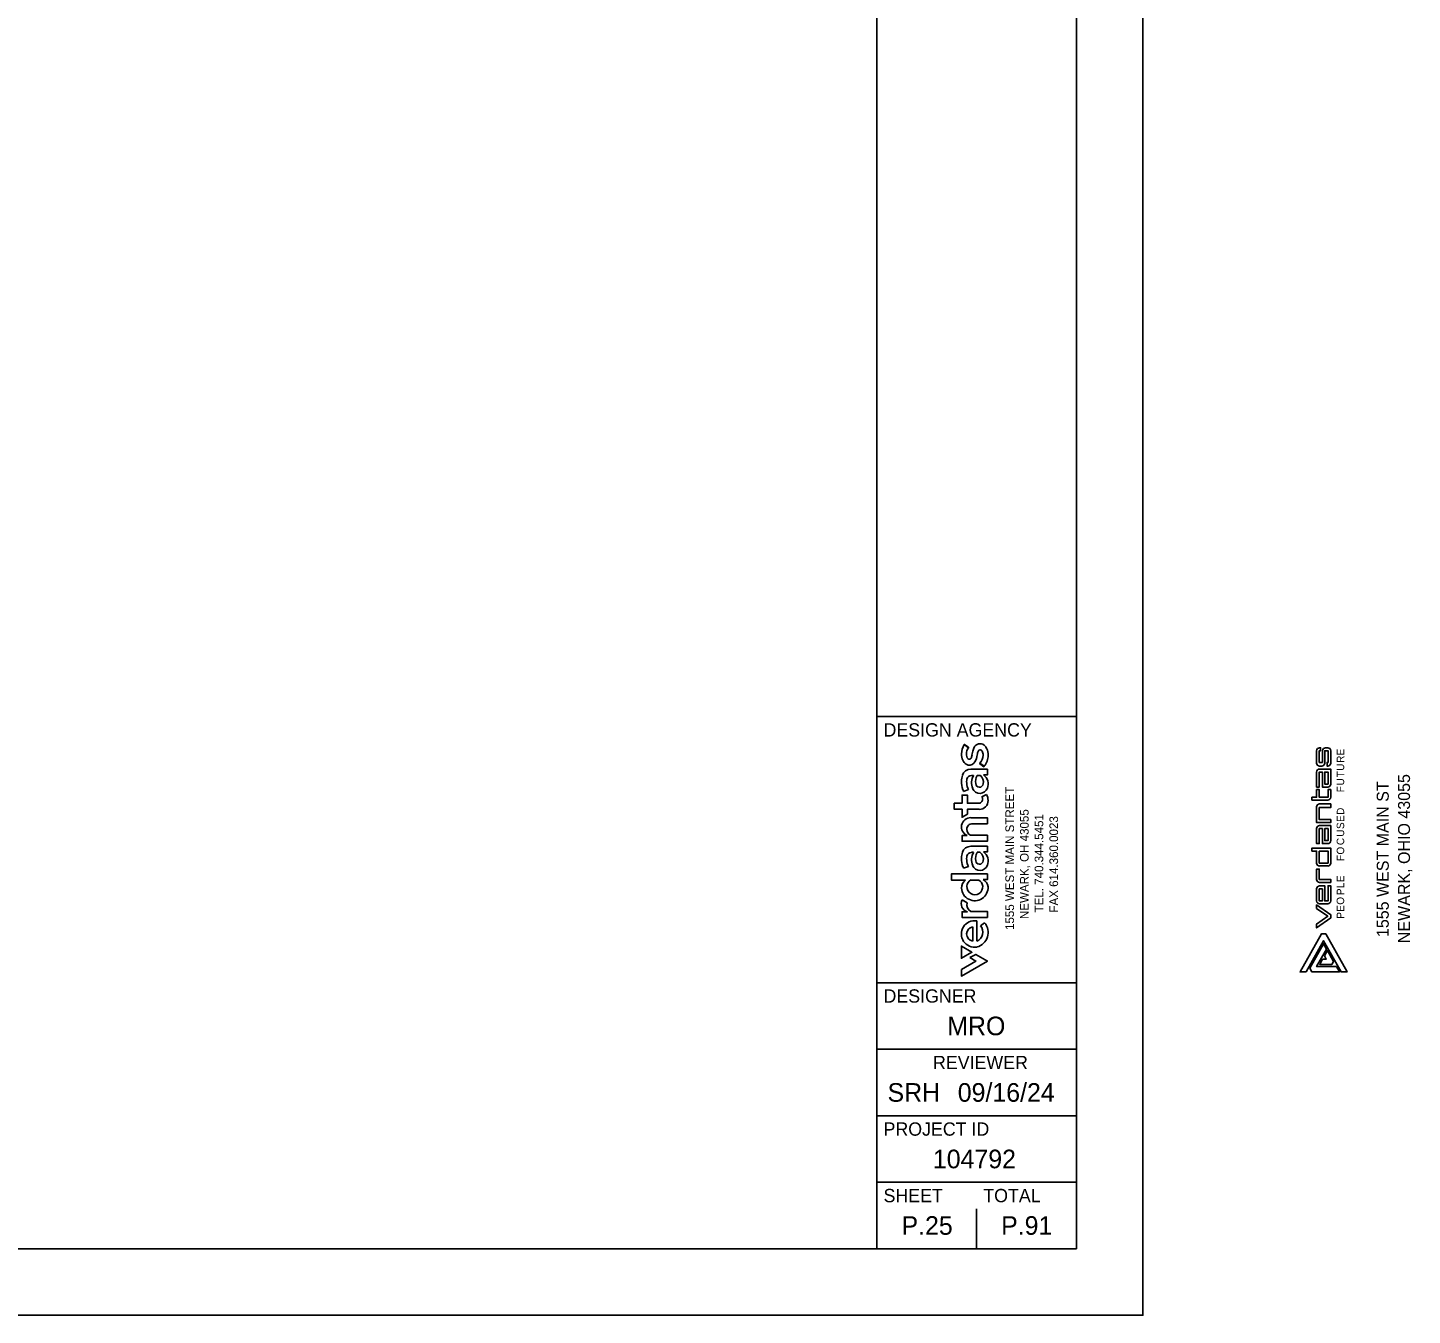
# Model space of a CAD drawing. Extents: x 0 to 36, y 0 to 22.
# Drawn here: x 25.62 to 36.03, y 0 to 9.68 of the extents above; entities that cross this region are included whole.
import ezdxf

# ---------------------------------------------------------------- set-up
doc = ezdxf.new("R2010")
doc.units = 0
for name, color, linetype in [('CS-ANNO-TTLB-LOGO', 7, 'Continuous'), ('Default', 7, 'Continuous'), ('SH_Border', 7, 'Continuous'), ('SH_Cut_Line', 7, 'Continuous'), ('SH_Data', 7, 'Continuous'), ('SH_Text', 7, 'Continuous')]:
    doc.layers.add(name, color=color, linetype=linetype)

msp = doc.modelspace()

# ---------------------------------------------------------------- linework, layer by layer
at = {"layer": 'CS-ANNO-TTLB-LOGO'}
for p, q in [((35.305, 4.243), (35.305, 4.15)), ((35.336, 4.266), (35.328, 4.266)), ((35.389, 4.266), (35.373, 4.266)), ((35.412, 4.15), (35.412, 4.243)), ((35.305, 3.97), (35.305, 4.083)), ((35.328, 4.128), (35.344, 4.128)), ((35.305, 3.546), (35.305, 3.658)), ((35.328, 3.377), (35.389, 3.377)), ((35.412, 3.115), (35.412, 3.228)), ((35.305, 3.205), (35.305, 3.115)), ((35.328, 3.093), (35.389, 3.093))]:
    msp.add_line(p, q, dxfattribs=at)
for points in [[(35.35, 4.243), (35.35, 4.156), (35.325, 4.156), (35.325, 4.243), (35.336, 4.243), (35.336, 4.266)], [(35.367, 4.15), (35.367, 4.243), (35.392, 4.243), (35.392, 4.156), (35.384, 4.156), (35.384, 4.128), (35.389, 4.128)], [(35.389, 3.97), (35.35, 3.97), (35.35, 4.083), (35.325, 4.083), (35.325, 3.97), (35.305, 3.97)], [(35.328, 4.105), (35.412, 4.105), (35.412, 3.993)], [(35.27, 3.894), (35.305, 3.894), (35.305, 3.951), (35.325, 3.951), (35.325, 3.894), (35.392, 3.894), (35.392, 3.951), (35.412, 3.951), (35.412, 3.894)], [(35.389, 3.872), (35.27, 3.872), (35.27, 3.894)], [(35.305, 3.821), (35.305, 3.703), (35.412, 3.703), (35.412, 3.726), (35.325, 3.726), (35.325, 3.816), (35.412, 3.816)], [(35.412, 3.816), (35.412, 3.844), (35.328, 3.844)], [(35.389, 3.546), (35.35, 3.546), (35.35, 3.658), (35.325, 3.658), (35.325, 3.546), (35.305, 3.546)], [(35.328, 3.681), (35.412, 3.681), (35.412, 3.568)], [(35.27, 3.512), (35.27, 3.489), (35.305, 3.489), (35.305, 3.399)], [(35.412, 3.399), (35.412, 3.512), (35.27, 3.512)], [(35.412, 3.276), (35.325, 3.276), (35.325, 3.354), (35.305, 3.354), (35.305, 3.276)], [(35.328, 3.253), (35.412, 3.253), (35.412, 3.276)], [(35.412, 3.228), (35.392, 3.228), (35.392, 3.115), (35.367, 3.115), (35.367, 3.228), (35.328, 3.228)]]:
    msp.add_lwpolyline(points, dxfattribs=at)
for points in [[(35.367, 4.083), (35.392, 4.083), (35.392, 3.993), (35.367, 3.993)], [(35.367, 3.658), (35.392, 3.658), (35.392, 3.568), (35.367, 3.568)], [(35.325, 3.489), (35.325, 3.399), (35.392, 3.399), (35.392, 3.489)], [(35.35, 3.205), (35.325, 3.205), (35.325, 3.115), (35.35, 3.115)], [(35.39, 2.999), (35.305, 2.94), (35.305, 2.912), (35.412, 2.987), (35.412, 3.011), (35.306, 3.085), (35.305, 3.058)]]:
    msp.add_lwpolyline(points, close=True, dxfattribs=at)
for centre, start, end in [((35.328, 4.243), 90, 180), ((35.373, 4.243), 90, 180), ((35.389, 4.243), 360, 90), ((35.328, 4.15), 180, 270), ((35.328, 4.083), 90, 180), ((35.344, 4.15), 270, 0), ((35.389, 4.15), 270, 0), ((35.389, 3.993), 270, 360), ((35.389, 3.894), 270, 360), ((35.328, 3.821), 90, 180), ((35.328, 3.658), 90, 180), ((35.389, 3.568), 270, 360), ((35.328, 3.399), 180, 270), ((35.389, 3.399), 270, 0), ((35.328, 3.276), 180, 270), ((35.328, 3.205), 90, 180), ((35.328, 3.115), 180, 270), ((35.389, 3.115), 270, 0)]:
    msp.add_arc(centre, 0.0225, start, end, dxfattribs=at)
at = {"layer": 'Default'}
for p, q in [((35.305, 4.243), (35.305, 4.15)), ((35.389, 4.266), (35.373, 4.266)), ((35.412, 4.15), (35.412, 4.243)), ((35.328, 4.128), (35.344, 4.128)), ((35.328, 3.377), (35.389, 3.377)), ((35.305, 3.205), (35.305, 3.115)), ((35.328, 3.093), (35.389, 3.093)), ((35.255, 2.609), (35.358, 2.792)), ((35.381, 2.752), (35.306, 2.621)), ((35.358, 2.792), (35.381, 2.752)), ((35.27, 2.581), (35.255, 2.609)), ((35.306, 2.621), (35.455, 2.621)), ((35.455, 2.621), (35.477, 2.581)), ((35.477, 2.581), (35.27, 2.581))]:
    msp.add_line(p, q, dxfattribs=at)
for points in [[(35.35, 4.243), (35.35, 4.156), (35.325, 4.156), (35.325, 4.243), (35.336, 4.243), (35.336, 4.266), (35.328, 4.266)], [(35.367, 4.15), (35.367, 4.243), (35.392, 4.243), (35.392, 4.156), (35.384, 4.156), (35.384, 4.128), (35.389, 4.128)], [(35.305, 4.083), (35.305, 3.97), (35.325, 3.97), (35.325, 4.083), (35.35, 4.083), (35.35, 3.97), (35.389, 3.97)], [(35.412, 3.993), (35.412, 4.105), (35.328, 4.105)], [(35.412, 3.894), (35.412, 3.951), (35.392, 3.951), (35.392, 3.894), (35.325, 3.894), (35.325, 3.951), (35.305, 3.951), (35.305, 3.894), (35.27, 3.894), (35.27, 3.872), (35.389, 3.872)], [(35.305, 3.821), (35.305, 3.703), (35.412, 3.703), (35.412, 3.726), (35.325, 3.726), (35.325, 3.816), (35.412, 3.816), (35.412, 3.844), (35.328, 3.844)], [(35.305, 3.658), (35.305, 3.546), (35.325, 3.546), (35.325, 3.658), (35.35, 3.658), (35.35, 3.546), (35.389, 3.546)], [(35.412, 3.568), (35.412, 3.681), (35.328, 3.681)], [(35.412, 3.399), (35.412, 3.512), (35.27, 3.512), (35.27, 3.489), (35.305, 3.489), (35.305, 3.399)], [(35.328, 3.253), (35.412, 3.253), (35.412, 3.276), (35.325, 3.276), (35.325, 3.354), (35.305, 3.354), (35.305, 3.276)], [(35.412, 3.115), (35.412, 3.228), (35.392, 3.228), (35.392, 3.115), (35.367, 3.115), (35.367, 3.228), (35.328, 3.228)]]:
    msp.add_lwpolyline(points, dxfattribs=at)
for points in [[(35.392, 4.083), (35.392, 3.993), (35.367, 3.993), (35.367, 4.083)], [(35.392, 3.658), (35.392, 3.568), (35.367, 3.568), (35.367, 3.658)], [(35.325, 3.489), (35.392, 3.489), (35.392, 3.399), (35.325, 3.399)], [(35.35, 3.205), (35.35, 3.115), (35.325, 3.115), (35.325, 3.205)], [(35.305, 2.94), (35.305, 2.912), (35.412, 2.987), (35.412, 3.011), (35.306, 3.085), (35.305, 3.058), (35.39, 2.999)], [(35.358, 2.815), (35.49, 2.581), (35.535, 2.581), (35.374, 2.867), (35.342, 2.867), (35.181, 2.581), (35.226, 2.581)], [(35.226, 2.581), (35.358, 2.815), (35.49, 2.581), (35.535, 2.581), (35.374, 2.867), (35.342, 2.867), (35.181, 2.581)], [(35.255, 2.609), (35.27, 2.581), (35.477, 2.581), (35.455, 2.621), (35.306, 2.621), (35.381, 2.752), (35.358, 2.792)], [(35.351, 2.677), (35.329, 2.637), (35.419, 2.637), (35.432, 2.66), (35.387, 2.741), (35.364, 2.701), (35.378, 2.677)], [(35.351, 2.677), (35.378, 2.677), (35.364, 2.701), (35.387, 2.741), (35.432, 2.66), (35.419, 2.637), (35.329, 2.637)]]:
    msp.add_lwpolyline(points, close=True, dxfattribs=at)
for centre, start, end in [((35.328, 4.243), 90, 180), ((35.373, 4.243), 90, 180), ((35.389, 4.243), 360, 90), ((35.328, 4.15), 180, 270), ((35.328, 4.083), 90, 180), ((35.344, 4.15), 270, 0), ((35.389, 4.15), 270, 0), ((35.389, 3.993), 270, 0), ((35.389, 3.894), 270, 0), ((35.328, 3.821), 90, 180), ((35.328, 3.658), 90, 180), ((35.389, 3.568), 270, 0), ((35.328, 3.399), 180, 270), ((35.389, 3.399), 270, 0), ((35.328, 3.276), 180, 270), ((35.328, 3.205), 90, 180), ((35.328, 3.115), 180, 270), ((35.389, 3.115), 270, 0)]:
    msp.add_arc(centre, 0.0225, start, end, dxfattribs=at)
at = {"layer": 'SH_Border'}
for p, q in [((32, 0.5), (32, 21.5)), ((32, 4.5), (33.5, 4.5)), ((32, 2.5), (33.5, 2.5)), ((32, 2), (33.5, 2)), ((32, 1.5), (33.5, 1.5)), ((32, 1), (33.5, 1))]:
    msp.add_line(p, q, dxfattribs=at)
msp.add_lwpolyline([(1.5, 21.5), (33.5, 21.5), (33.5, 0.5), (1.5, 0.5)], close=True, dxfattribs=at)
at = {"layer": 'SH_Cut_Line'}
msp.add_lwpolyline([(0, 0), (34, 0), (34, 22), (0, 22)], close=True, dxfattribs=at)
at = {"layer": 'SH_Data'}
for p, q in [((32.75, 3.5), (32.75, 3.5)), ((32.75, 0.5), (32.75, 0.8)), ((32.375, 0.675), (32.375, 0.675))]:
    msp.add_line(p, q, dxfattribs=at)
at = {"layer": 'SH_Text'}
for p, q in [((32.688, 4.266), (32.657, 4.29)), ((32.722, 4.24), (32.715, 4.209)), ((32.751, 4.199), (32.756, 4.219)), ((32.774, 4.151), (32.807, 4.127)), ((32.711, 4.058), (32.727, 4.058)), ((32.753, 4.058), (32.776, 4.058)), ((32.648, 3.95), (32.652, 3.938)), ((32.825, 3.914), (32.79, 3.898)), ((32.711, 3.48), (32.727, 3.48)), ((32.753, 3.48), (32.776, 3.48)), ((32.648, 3.372), (32.652, 3.36)), ((32.706, 3.271), (32.766, 3.271)), ((32.679, 3.1), (32.642, 3.122)), ((32.721, 2.92), (32.721, 2.812)), ((32.751, 2.811), (32.751, 2.964)), ((32.81, 2.95), (32.778, 2.928))]:
    msp.add_line(p, q, dxfattribs=at)
for points in [[(32.689, 4.269), (32.658, 4.291), (32.657, 4.29)], [(32.688, 4.266), (32.689, 4.269)], [(32.722, 4.24), (32.715, 4.209)], [(32.751, 4.199), (32.756, 4.219)], [(32.801, 4.062), (32.831, 4.062), (32.831, 4.104), (32.706, 4.104)], [(32.801, 4.062), (32.831, 4.062), (32.831, 4.104), (32.706, 4.104)], [(32.774, 4.151), (32.772, 4.148), (32.803, 4.123), (32.807, 4.127)], [(32.652, 3.938), (32.688, 3.953), (32.684, 3.962)], [(32.652, 3.938), (32.688, 3.953), (32.684, 3.962)], [(32.711, 4.058), (32.727, 4.058)], [(32.776, 4.058), (32.753, 4.058)], [(32.762, 3.849), (32.68, 3.849), (32.68, 3.91), (32.641, 3.91), (32.641, 3.849), (32.582, 3.849), (32.582, 3.803), (32.641, 3.803), (32.641, 3.744), (32.68, 3.767), (32.68, 3.803), (32.77, 3.803)], [(32.762, 3.849), (32.68, 3.849), (32.68, 3.91), (32.641, 3.91), (32.641, 3.849), (32.582, 3.849), (32.582, 3.803), (32.641, 3.803), (32.641, 3.744), (32.68, 3.767), (32.68, 3.803), (32.77, 3.803)], [(32.648, 3.95), (32.652, 3.938)], [(32.825, 3.914), (32.79, 3.898)], [(32.72, 3.694), (32.831, 3.694), (32.831, 3.74), (32.707, 3.74)], [(32.72, 3.694), (32.831, 3.694), (32.831, 3.74), (32.707, 3.74)], [(32.678, 3.605), (32.641, 3.605), (32.641, 3.563), (32.831, 3.563), (32.831, 3.608), (32.704, 3.608)], [(32.678, 3.605), (32.641, 3.605), (32.641, 3.563), (32.831, 3.563), (32.831, 3.608), (32.704, 3.608)], [(32.801, 3.483), (32.831, 3.483), (32.831, 3.525), (32.706, 3.525)], [(32.801, 3.483), (32.831, 3.483), (32.831, 3.525), (32.706, 3.525)], [(32.711, 3.48), (32.727, 3.48)], [(32.776, 3.48), (32.753, 3.48)], [(32.648, 3.372), (32.652, 3.36)], [(32.652, 3.36), (32.688, 3.374), (32.684, 3.384)], [(32.652, 3.36), (32.688, 3.374), (32.684, 3.384)], [(32.667, 3.271), (32.56, 3.271), (32.56, 3.317), (32.831, 3.317), (32.831, 3.275), (32.798, 3.275)], [(32.798, 3.275), (32.831, 3.275), (32.831, 3.317), (32.56, 3.317), (32.56, 3.271), (32.667, 3.271)], [(32.706, 3.271), (32.766, 3.271)], [(32.682, 3.033), (32.641, 3.033), (32.641, 2.991), (32.831, 2.991), (32.831, 3.035), (32.705, 3.035)], [(32.682, 3.033), (32.641, 3.033), (32.641, 2.991), (32.831, 2.991), (32.831, 3.035), (32.705, 3.035)], [(32.679, 3.1), (32.642, 3.122)], [(32.721, 2.812), (32.721, 2.92)], [(32.751, 2.811), (32.751, 2.964)], [(32.81, 2.95), (32.778, 2.928)], [(32.636, 2.775), (32.636, 2.684), (32.714, 2.729), (32.636, 2.775)], [(32.7, 2.688), (32.744, 2.662), (32.636, 2.599), (32.636, 2.549), (32.831, 2.662), (32.743, 2.713), (32.7, 2.688)]]:
    msp.add_lwpolyline(points, dxfattribs=at)
for points in [[(32.714, 2.729), (32.636, 2.684), (32.636, 2.775)], [(32.7, 2.688), (32.744, 2.662), (32.636, 2.599), (32.636, 2.549), (32.831, 2.662), (32.743, 2.713)]]:
    msp.add_lwpolyline(points, close=True, dxfattribs=at)
for centre, radius, start, end in [((32.767, 4.219), 0.131, 147.2233, 179.842), ((32.767, 4.219), 0.131, 147.2233, 179.842), ((32.849, 4.212), 0.13, 154.0447, 167.2149), ((32.849, 4.212), 0.13, 154.0447, 167.2149), ((32.776, 4.247), 0.0493, 52.7092, 154.2166), ((32.776, 4.247), 0.0493, 52.7092, 154.2166), ((32.761, 4.231), 0.0711, 22.8278, 50.7157), ((32.761, 4.231), 0.0711, 22.8278, 50.7157), ((32.75, 4.217), 0.114, 179.0109, 203.56), ((32.75, 4.217), 0.114, 179.0109, 203.56), ((32.707, 4.198), 0.067, 203.3692, 237.807), ((32.707, 4.198), 0.067, 203.3692, 237.807), ((32.768, 4.216), 0.0948, 148.1233, 178.1135), ((32.768, 4.216), 0.0948, 148.1233, 178.1135), ((32.744, 4.218), 0.0702, 179.0539, 195.6921), ((32.744, 4.218), 0.0702, 179.0539, 195.6921), ((32.709, 4.207), 0.0335, 193.8561, 223.7191), ((32.709, 4.207), 0.0335, 193.8561, 223.7191), ((32.695, 4.194), 0.0148, 224.7822, 330.4366), ((32.695, 4.194), 0.0148, 224.7822, 330.4366), ((32.635, 4.224), 0.0819, 332.9002, 349.3831), ((32.635, 4.224), 0.0819, 332.9002, 349.3831), ((32.648, 4.217), 0.105, 320.1259, 349.7023), ((32.648, 4.217), 0.105, 320.1259, 349.7023), ((32.849, 4.203), 0.0949, 158.1863, 170.6328), ((32.849, 4.203), 0.0949, 158.1863, 170.6328), ((32.777, 4.234), 0.0165, 26.9165, 163.602), ((32.777, 4.234), 0.0165, 26.9165, 163.602), ((32.705, 4.214), 0.0932, 317.363, 356.9244), ((32.705, 4.214), 0.0932, 317.363, 356.9244), ((32.733, 4.212), 0.0655, 357.0077, 26.3112), ((32.733, 4.212), 0.0655, 357.0077, 26.3112), ((32.707, 4.209), 0.129, 320.5166, 0.4341), ((32.707, 4.209), 0.129, 320.5166, 0.4341), ((32.717, 4.212), 0.12, 359.0192, 22.9257), ((32.717, 4.212), 0.12, 359.0192, 22.9257), ((32.704, 4.04), 0.0639, 88.076, 162.8642), ((32.704, 4.04), 0.0639, 88.076, 162.8642), ((32.695, 4.181), 0.0458, 238.9453, 317.6829), ((32.695, 4.181), 0.0458, 238.9453, 317.6829), ((32.751, 3.993), 0.0857, 338.2774, 53.7949), ((32.751, 3.993), 0.0857, 338.2774, 53.7949), ((32.764, 4.016), 0.128, 160.8128, 180.9317), ((32.764, 4.016), 0.128, 160.8128, 180.9317), ((32.834, 4.018), 0.199, 180.9467, 199.8354), ((32.834, 4.018), 0.199, 180.9467, 199.8354), ((32.739, 4.012), 0.0647, 163.2522, 179.9971), ((32.739, 4.012), 0.0647, 163.2522, 179.9971), ((32.826, 4.016), 0.152, 181.6616, 200.8714), ((32.826, 4.016), 0.152, 181.6616, 200.8714), ((32.713, 4.021), 0.0374, 92.9671, 165.223), ((32.713, 4.021), 0.0374, 92.9671, 165.223), ((32.82, 4.001), 0.108, 148.3497, 202.4708), ((32.82, 4.001), 0.108, 148.3497, 202.4708), ((32.775, 3.982), 0.0592, 201.6764, 339.7268), ((32.775, 3.982), 0.0592, 201.6764, 339.7268), ((32.847, 4.012), 0.105, 153.8372, 188.8746), ((32.847, 4.012), 0.105, 153.8372, 188.8746), ((32.771, 3.997), 0.0281, 182.327, 355.3778), ((32.771, 3.997), 0.0281, 182.327, 355.3778), ((32.737, 4.008), 0.0637, 348.1247, 52.3678), ((32.737, 4.008), 0.0637, 348.1247, 52.3678), ((32.764, 3.88), 0.0314, 265.0692, 356.3548), ((32.764, 3.88), 0.0314, 265.0692, 356.3548), ((32.772, 3.867), 0.0642, 267.8641, 1.6213), ((32.772, 3.867), 0.0642, 267.8641, 1.6213), ((32.752, 3.877), 0.0432, 1.8638, 29.9651), ((32.752, 3.877), 0.0432, 1.8638, 29.9651), ((32.742, 3.87), 0.0939, 359.5424, 28.2495), ((32.742, 3.87), 0.0939, 359.5424, 28.2495), ((32.706, 3.67), 0.0703, 88.9896, 246.9111), ((32.706, 3.67), 0.0703, 88.9896, 246.9111), ((32.72, 3.654), 0.0434, 137.3049, 182.9688), ((32.72, 3.654), 0.0434, 137.3049, 182.9688), ((32.724, 3.652), 0.0477, 180.3466, 244.9113), ((32.724, 3.652), 0.0477, 180.3466, 244.9113), ((32.717, 3.651), 0.0433, 86.9739, 132.7421), ((32.717, 3.651), 0.0433, 86.9739, 132.7421), ((32.764, 3.438), 0.128, 160.8128, 180.9317), ((32.764, 3.438), 0.128, 160.8128, 180.9317), ((32.834, 3.439), 0.199, 180.9467, 199.8354), ((32.834, 3.439), 0.199, 180.9467, 199.8354), ((32.704, 3.461), 0.0639, 88.076, 162.8642), ((32.704, 3.461), 0.0639, 88.076, 162.8642), ((32.739, 3.433), 0.0647, 163.2522, 179.9971), ((32.739, 3.433), 0.0647, 163.2522, 179.9971), ((32.713, 3.442), 0.0374, 92.9671, 165.223), ((32.713, 3.442), 0.0374, 92.9671, 165.223), ((32.82, 3.423), 0.108, 148.3497, 202.4708), ((32.82, 3.423), 0.108, 148.3497, 202.4708), ((32.847, 3.433), 0.105, 153.8372, 188.8746), ((32.847, 3.433), 0.105, 153.8372, 188.8746), ((32.737, 3.429), 0.0637, 348.1247, 52.3678), ((32.737, 3.429), 0.0637, 348.1247, 52.3678), ((32.751, 3.414), 0.0857, 338.2774, 53.7949), ((32.751, 3.414), 0.0857, 338.2774, 53.7949), ((32.826, 3.438), 0.152, 181.6616, 200.8714), ((32.826, 3.438), 0.152, 181.6616, 200.8714), ((32.775, 3.403), 0.0592, 201.6764, 339.7268), ((32.775, 3.403), 0.0592, 201.6764, 339.7268), ((32.771, 3.418), 0.0281, 182.327, 355.3778), ((32.771, 3.418), 0.0281, 182.327, 355.3778), ((32.707, 3.212), 0.0714, 124.2843, 181.2723), ((32.707, 3.212), 0.0714, 124.2843, 181.2723), ((32.735, 3.221), 0.0586, 119.9007, 175.5797), ((32.735, 3.221), 0.0586, 119.9007, 175.5797), ((32.737, 3.22), 0.0588, 6.0666, 60.041), ((32.737, 3.22), 0.0588, 6.0666, 60.041), ((32.769, 3.215), 0.0671, 5.3084, 64.5252), ((32.769, 3.215), 0.0671, 5.3084, 64.5252), ((32.736, 3.216), 0.1, 182.7719, 2.9779), ((32.736, 3.216), 0.1, 182.7719, 2.9779), ((32.736, 3.221), 0.0595, 176.4529, 5.055), ((32.736, 3.221), 0.0595, 176.4529, 5.055), ((32.697, 3.094), 0.0628, 152.6524, 255.2929), ((32.697, 3.094), 0.0628, 152.6524, 255.2929), ((32.731, 3.083), 0.0545, 162.1384, 242.0408), ((32.731, 3.083), 0.0545, 162.1384, 242.0408), ((32.735, 2.866), 0.0996, 81.0446, 280.2577), ((32.735, 2.866), 0.0996, 81.0446, 280.2577), ((32.729, 2.866), 0.0543, 98.8378, 261.1622), ((32.729, 2.866), 0.0543, 98.8378, 261.1622), ((32.725, 2.879), 0.072, 290.9232, 42.7391), ((32.725, 2.879), 0.072, 290.9232, 42.7391), ((32.722, 2.878), 0.114, 285.6668, 39.3699), ((32.722, 2.878), 0.114, 285.6668, 39.3699)]:
    msp.add_arc(centre, radius, start, end, dxfattribs=at)

# ---------------------------------------------------------------- texts
at = {"layer": 'Default'}
for s, p in [('E', (35.513, 4.208)), ('R', (35.513, 4.152)), ('U', (35.513, 4.092)), ('T', (35.513, 4.043)), ('U', (35.513, 3.982)), ('F', (35.513, 3.931)), ('D', (35.513, 3.761)), ('E', (35.513, 3.708)), ('S', (35.513, 3.655)), ('U', (35.513, 3.597)), ('C', (35.513, 3.534)), ('O', (35.513, 3.463)), ('F', (35.513, 3.414)), ('E', (35.513, 3.256)), ('L', (35.513, 3.21)), ('P', (35.513, 3.158)), ('O', (35.513, 3.086)), ('E', (35.513, 3.033)), ('P', (35.513, 2.981))]:
    msp.add_text(s, height=0.0563, rotation=90, dxfattribs=at).set_placement(p)
at = {"layer": 'SH_Data'}
for s, height, p in [('DESIGN AGENCY', 0.1, (32.05, 4.35)), ('DESIGNER', 0.1, (32.05, 2.35)), ('MRO', 0.14, (32.529, 2.105)), ('REVIEWER', 0.1, (32.422, 1.85)), ('SRH', 0.14, (32.08, 1.605)), ('09/16/24', 0.14, (32.608, 1.605)), ('PROJECT ID', 0.1, (32.05, 1.35)), ('104792', 0.14, (32.421, 1.105)), ('SHEET', 0.1, (32.05, 0.85)), ('TOTAL', 0.1, (32.8, 0.85)), ('P.25', 0.14, (32.185, 0.605)), ('P.91', 0.14, (32.934, 0.605))]:
    msp.add_text(s, height=height, dxfattribs=at).set_placement(p)
at = {"layer": 'SH_Text'}
for s, height, p in [('NEWARK, OHIO 43055', 0.09, (36.008, 2.797)), ('1555 WEST MAIN STREET', 0.06497, (33.031, 2.896)), ('1555 WEST MAIN ST', 0.09, (35.848, 2.843)), ('NEWARK, OH 43055', 0.06497, (33.141, 2.978)), ('TEL. 740.344.5451', 0.06497, (33.251, 3.028)), ('FAX 614.360.0023', 0.06497, (33.362, 3.027))]:
    msp.add_text(s, height=height, rotation=90, dxfattribs=at).set_placement(p)

doc.saveas('drawing.dxf')
